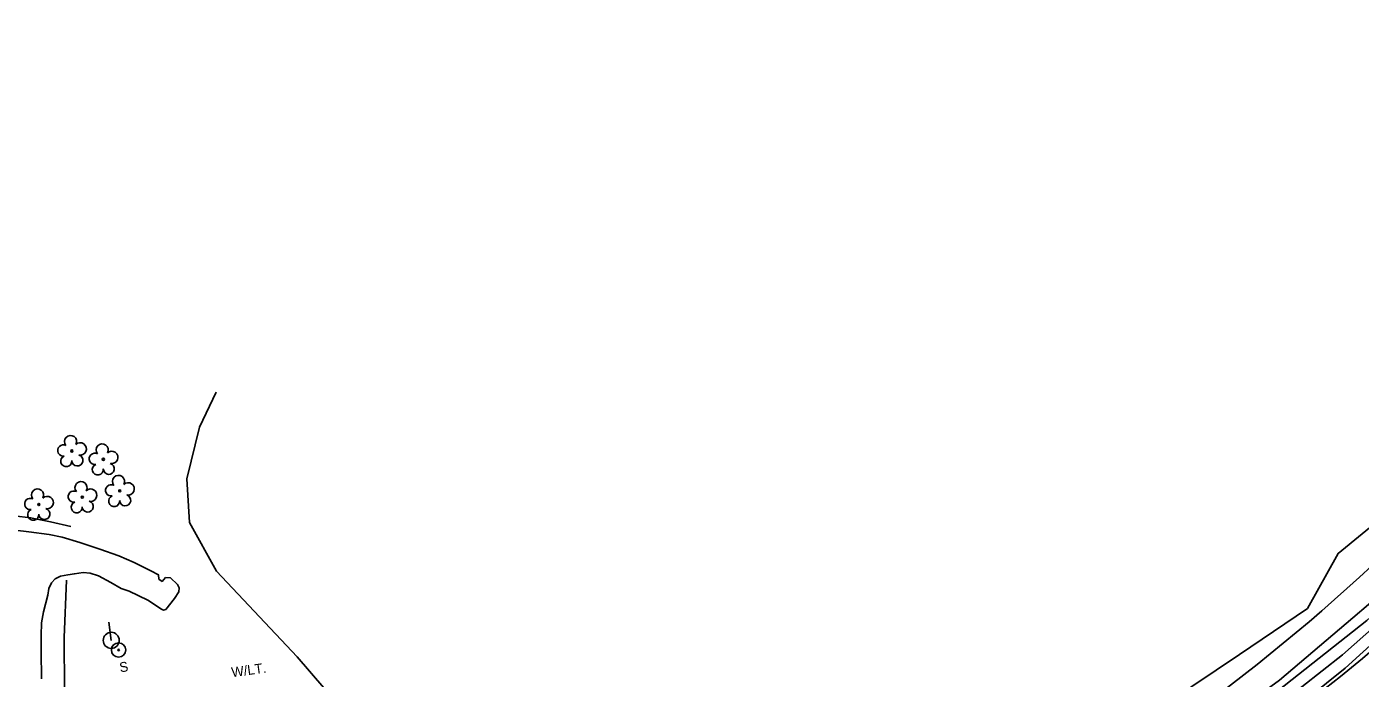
# Model space of a CAD drawing. Extents: x 1645945 to 2447332, y 713118 to 970361.
# Drawn here: x 1647146.3 to 1647554, y 969737.2 to 969936.3 of the extents above; entities that cross this region are included whole.
import ezdxf

# ---------------------------------------------------------------- set-up
doc = ezdxf.new("R2010")
doc.units = 0
for name, color, linetype in [('Exist Horizontal Alignment', 7, 'Continuous'), ('Exist Other Culture Fence Line', 7, 'Continuous'), ('Exist Other Culture Located Object CELL', 7, 'Continuous'), ('Exist Other Culture Located Object Text', 7, 'Continuous'), ('Exist Right of Way Line', 7, 'Continuous'), ('Exist Roads EOP', 7, 'Continuous'), ('Exist Roads EOP Other', 7, 'Continuous'), ('Exist Utilities Power Pole CELL', 7, 'Continuous'), ('Exist Utilities Power Pole Text', 7, 'Continuous'), ('Exist Utilities Telephone UG Cable SUE LOS C', 7, 'Continuous'), ('Exist Utilities Telephone UG FO SUE LOS C', 7, 'Continuous'), ('Exist Vegetation Tree CELL', 7, 'Continuous'), ('Exist Vegetation Woods Line', 7, 'Continuous')]:
    doc.layers.add(name, color=color, linetype=linetype)

msp = doc.modelspace()

# ---------------------------------------------------------------- linework, layer by layer
at = {"layer": 'Exist Horizontal Alignment'}
msp.add_arc((1647126.83, 970240.1), 665, 298.87121, 329.93673, dxfattribs=at)
at = {"layer": 'Exist Other Culture Fence Line'}
for points in [[(1647092.77, 969786.54), (1647102.32, 969788.59), (1647107.68, 969789.68), (1647116.05, 969789.06), (1647124.24, 969788.6), (1647137.45, 969787.52), (1647147.52, 969786.3), (1647153.58, 969785.04), (1647159.81, 969783.63)], [(1647158.47, 969767.25), (1647158.47, 969767.24), (1647157.76, 969749.69), (1647157.9, 969733.64), (1647156.59, 969712.7), (1647155.3, 969692.94), (1647154.95, 969677.36), (1647154.34, 969660.7), (1647154.18, 969651.66)]]:
    msp.add_lwpolyline(points, dxfattribs=at)
at = {"layer": 'Exist Other Culture Located Object CELL'}
for radius in [2.18, 0.24]:
    msp.add_circle((1647174.41, 969745.89), radius, dxfattribs=at)
at = {"layer": 'Exist Right of Way Line'}
for radius in [620, 680]:
    msp.add_arc((1647136.28, 970226.5), radius, 299.46236, 329.93673, dxfattribs=at)
at = {"layer": 'Exist Roads EOP'}
for points in [[(1647712.71, 969946.05), (1647689.83, 969906.56), (1647665.85, 969869.13), (1647637.34, 969829.12), (1647607.92, 969794.57), (1647574.53, 969760.72), (1647538.69, 969730.5), (1647499.85, 969702.79), (1647457.34, 969676.33), (1647411.66, 969651.37), (1647366.8, 969630.41), (1647321.37, 969611.83), (1647279.28, 969597.97), (1647224.82, 969583.15), (1647179.92, 969574.15), (1647132.17, 969565.53), (1647083.22, 969557.97), (1647036.22, 969550.58), (1646989.26, 969543.73)], [(1647731.3, 969935.45), (1647707.71, 969895.07), (1647684.27, 969857.13), (1647654.38, 969814.5), (1647624.46, 969779.25), (1647589.97, 969744.66), (1647553.5, 969714.01), (1647512.43, 969684.95), (1647469.3, 969658.19), (1647421.26, 969632.07), (1647375.68, 969609.9), (1647329.15, 969590.49), (1647286.02, 969576.26), (1647230.19, 969561.18), (1647183.04, 969552.75), (1647135.89, 969544.58), (1647086.4, 969536.99), (1647040.14, 969529.53), (1646992.05, 969522.32)]]:
    msp.add_spline(points, degree=3, dxfattribs=at)
at = {"layer": 'Exist Roads EOP Other'}
msp.add_lwpolyline([(1647136.02, 969783.35), (1647147.01, 969781.95), (1647153.2, 969781.15), (1647157.14, 969780.33), (1647162.6, 969778.7), (1647168.72, 969776.71), (1647174.5, 969774.69), (1647179.23, 969772.59), (1647184.27, 969770.11), (1647186.61, 969768.88), (1647186.76, 969767.55), (1647187.71, 969766.84), (1647188.77, 969768.07), (1647190.28, 969767.88), (1647192.46, 969765.93), (1647192.93, 969764.91), (1647192.8, 969763.6), (1647191.51, 969761.65), (1647188.81, 969758.23), (1647188.15, 969758.09), (1647187.51, 969758.34), (1647183.31, 969761.14), (1647177.66, 969763.84), (1647175.24, 969764.65), (1647172.05, 969766.52), (1647168.23, 969768.56), (1647165.75, 969769.33), (1647163.56, 969769.51), (1647160.92, 969769.19), (1647158.91, 969768.82), (1647156.65, 969768.39), (1647155.06, 969767.57), (1647153.86, 969766.36), (1647153.08, 969764.65), (1647152.75, 969762.65), (1647151.46, 969757.51), (1647150.88, 969754.2), (1647150.7, 969750.36), (1647150.73, 969745.46), (1647150.83, 969737.05)], dxfattribs=at)
at = {"layer": 'Exist Utilities Power Pole CELL'}
for q in [(1647171.42, 969754.4), (1647172.17, 969748.83)]:
    msp.add_line((1647172.17, 969748.83), q, dxfattribs=at)
msp.add_circle((1647172.17, 969748.83), 2.45, dxfattribs=at)
at = {"layer": 'Exist Utilities Telephone UG Cable SUE LOS C'}
for points in [[(1647301.18, 969607.49), (1647346.35, 969625.33), (1647402.72, 969651.12), (1647431.08, 969666.24), (1647439.41, 969670.62), (1647442.16, 969672.78), (1647445.5, 969676.48), (1647448.63, 969678.56), (1647474.06, 969693.41), (1647520.52, 969726.92), (1647556, 969754.87), (1647590.11, 969785.42), (1647617.35, 969813.54), (1647647.46, 969852.3), (1647702.67, 969945.18), (1647775.84, 970087.47)], [(1647299.74, 969604.87), (1647344.43, 969621.93), (1647402.05, 969647.91), (1647428.7, 969661.61), (1647441.47, 969668.79), (1647444.57, 969671.27), (1647446.47, 969673.44), (1647447.93, 969674.84), (1647451.1, 969676.98), (1647475.41, 969691.19), (1647501.84, 969708.82), (1647529.96, 969729.71), (1647548.6, 969744.41), (1647576.21, 969768.81), (1647599.16, 969791.2), (1647624.94, 969819.94), (1647649.96, 969852.56), (1647680.88, 969902.23), (1647705.82, 969944.72), (1647779.36, 970085.84)]]:
    msp.add_lwpolyline(points, dxfattribs=at)
at = {"layer": 'Exist Utilities Telephone UG FO SUE LOS C'}
for points in [[(1647289.7, 969609.34), (1647343.59, 969629.58), (1647397.62, 969653.63), (1647450.96, 969681.88), (1647471.14, 969694.21), (1647529.28, 969736.65), (1647578.89, 969778.78), (1647616.07, 969816.36), (1647645.02, 969855.2), (1647696.33, 969943.83), (1647771.33, 970089.55)], [(1647291.19, 969605.96), (1647345.09, 969627.35), (1647401.66, 969653.17), (1647434.03, 969670.53), (1647438.26, 969672.06), (1647445.18, 969672.38), (1647450.09, 969673.09), (1647455.34, 969675.46), (1647473.43, 969686.09), (1647508.86, 969709.29), (1647532.76, 969727.04), (1647549.35, 969740.28), (1647575.78, 969764.21), (1647609.03, 969797.83), (1647638.13, 969832.64), (1647665.39, 969871.17), (1647698.7, 969925.68), (1647740.76, 970001.75), (1647782.56, 970084.37)]]:
    msp.add_lwpolyline(points, dxfattribs=at)
at = {"layer": 'Exist Vegetation Tree CELL'}
for p, q in [((1647160.13, 969806.69), (1647160.13, 969806.69)), ((1647169.77, 969804.13), (1647169.77, 969804.13)), ((1647174.77, 969794.5), (1647174.77, 969794.5)), ((1647150.04, 969790.33), (1647150.04, 969790.33)), ((1647163.32, 969792.59), (1647163.32, 969792.59))]:
    msp.add_line(p, q, dxfattribs=at)
for centre in [(1647160.13, 969806.69), (1647169.77, 969804.13), (1647174.77, 969794.5), (1647150.04, 969790.33), (1647163.32, 969792.59)]:
    msp.add_circle(centre, 0.326, dxfattribs=at)
for centre, radius, start, end in [((1647159.75, 969809.56), 1.86, 330.1651, 219.7134), ((1647157.53, 969806.84), 1.73, 62.6636, 279.3457), ((1647162.68, 969807.28), 1.9, 257.1011, 134.1999), ((1647169.39, 969807.01), 1.86, 330.1651, 219.7134), ((1647172.32, 969804.72), 1.9, 257.1011, 134.1999), ((1647158.43, 969803.57), 1.69, 111.5671, 6.231), ((1647161.81, 969803.79), 1.7, 181.2822, 74.56), ((1647167.17, 969804.29), 1.73, 62.6636, 279.3457), ((1647168.07, 969801.01), 1.69, 111.5671, 6.231), ((1647171.44, 969801.23), 1.7, 181.2822, 74.56), ((1647174.39, 969797.37), 1.86, 330.1651, 219.7134), ((1647149.65, 969793.21), 1.86, 330.1651, 219.7134), ((1647160.72, 969792.74), 1.73, 62.6636, 279.3457), ((1647162.94, 969795.46), 1.86, 330.1651, 219.7134), ((1647165.87, 969793.18), 1.9, 257.1011, 134.1999), ((1647172.17, 969794.65), 1.73, 62.6636, 279.3457), ((1647177.32, 969795.09), 1.9, 257.1011, 134.1999), ((1647147.43, 969790.49), 1.73, 62.6636, 279.3457), ((1647152.59, 969790.92), 1.9, 257.1011, 134.1999), ((1647161.62, 969789.47), 1.69, 111.5671, 6.231), ((1647164.99, 969789.69), 1.7, 181.2822, 74.56), ((1647173.07, 969791.38), 1.69, 111.5671, 6.231), ((1647176.44, 969791.6), 1.7, 181.2822, 74.56), ((1647148.33, 969787.21), 1.69, 111.5671, 6.231), ((1647151.71, 969787.43), 1.7, 181.2822, 74.56)]:
    msp.add_arc(centre, radius, start, end, dxfattribs=at)
at = {"layer": 'Exist Vegetation Woods Line'}
for points in [[(1647237.13, 969734.31), (1647228.98, 969743.77), (1647204.33, 969770), (1647196.09, 969784.79), (1647195.3, 969798.18), (1647199.16, 969813.99), (1647204.27, 969824.68)], [(1647575.42, 969798.45), (1647547.21, 969775.36), (1647537.84, 969758.54), (1647517.03, 969744.5), (1647495.35, 969729.99)]]:
    msp.add_lwpolyline(points, dxfattribs=at)

# ---------------------------------------------------------------- texts
at = {"layer": 'Exist Other Culture Located Object Text'}
msp.add_text('S', height=3, rotation=8.7749, dxfattribs=at).set_placement((1647174.91, 969739.04))
at = {"layer": 'Exist Utilities Power Pole Text'}
msp.add_text('W/LT.', height=3, rotation=7.7882, dxfattribs=at).set_placement((1647209.13, 969737.55))

doc.saveas('drawing.dxf')
